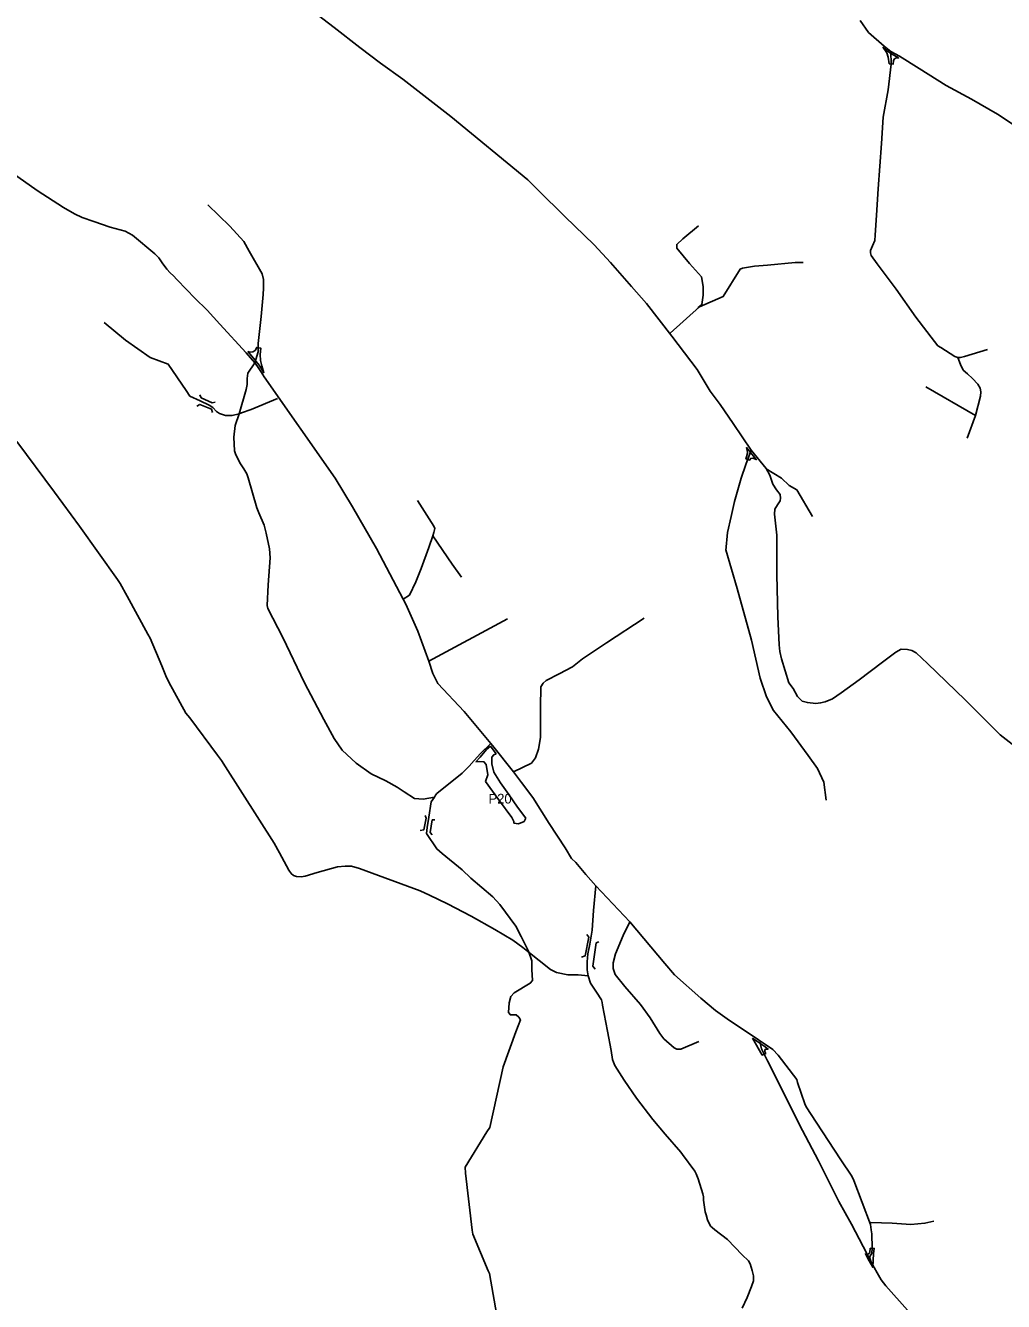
# Model space of a CAD drawing. Extents: x -439169 to -431590, y -1130011 to -1121081.
# Drawn here: x -437746 to -436739, y -1125656 to -1124342 of the extents above; entities that cross this region are included whole.
import ezdxf

# ---------------------------------------------------------------- set-up
doc = ezdxf.new("R2010")
doc.units = 0
for name, color, linetype in [('11811012_místní  komunikace_Stav', 7, 'Continuous'), ('11900012_účelová komunikace_Stav', 7, 'Continuous'), ('11930011_silniční most _ estakáda_Stav', 7, 'Continuous'), ('12080011_parkoviště mimo prostor komunikace_Stav', 7, 'Continuous'), ('12080013_parkoviště mimo prostor komunikace_Stav', 7, 'Continuous')]:
    doc.layers.add(name, color=color, linetype=linetype)

msp = doc.modelspace()

# ---------------------------------------------------------------- linework, layer by layer
at = {"layer": '11811012_místní  komunikace_Stav'}
msp.add_line((-437164.8, -1125287.2), (-437164.6, -1125287.3), dxfattribs=at)
for points in [[(-437450.2, -1124327.5), (-437428.1, -1124344.3), (-437401.6, -1124365), (-437380.4, -1124381), (-437357.4, -1124397.8), (-437307.9, -1124435.9), (-437228.9, -1124501.3), (-437218, -1124511.9), (-437190.5, -1124539), (-437160.3, -1124568.3), (-437143.6, -1124586.2), (-437122, -1124610.9), (-437106.5, -1124628.5), (-437080.4, -1124662.1), (-437054.4, -1124696.6), (-437041, -1124718.7), (-437030.6, -1124732.4), (-437017.3, -1124752), (-436999, -1124779.6), (-436983.5, -1124798.5), (-436979.6, -1124805.1), (-436976.6, -1124814.5), (-436972.9, -1124820.4), (-436968.9, -1124825.2), (-436968.5, -1124828.8), (-436969.1, -1124831.7), (-436971.6, -1124835.7), (-436974.4, -1124840.3), (-436974.8, -1124845.5), (-436972.3, -1124867), (-436972.4, -1124907.4), (-436971.3, -1124951), (-436969.9, -1124979.8), (-436969.3, -1124986.9), (-436967.7, -1124994.3), (-436960.1, -1125019.2), (-436955.8, -1125024.9), (-436951.2, -1125033.1), (-436948.4, -1125035.8), (-436946.3, -1125038), (-436940.9, -1125039.3), (-436932.4, -1125040.4), (-436927.4, -1125039.7), (-436922.6, -1125038.7), (-436915.3, -1125035.4), (-436906.1, -1125029.3), (-436887.6, -1125016), (-436863.8, -1124997.6), (-436850, -1124987.3), (-436844.6, -1124984.5), (-436838.1, -1124984.7), (-436833.4, -1124985.8), (-436829, -1124988.2), (-436817.2, -1124999.1), (-436778.5, -1125036.6), (-436742.4, -1125072.6), (-436719.4, -1125090.7)], [(-436886.5, -1124337.3), (-436878.1, -1124349.5), (-436861.8, -1124363.5), (-436855.1, -1124369), (-436846.2, -1124374), (-436826.1, -1124386.5), (-436798.3, -1124404.1), (-436772, -1124418.3), (-436745.3, -1124433.5), (-436718.8, -1124451)], [(-436855.1, -1124369), (-436854.7, -1124382.1), (-436857.8, -1124408.7), (-436863, -1124436.7), (-436864.8, -1124464), (-436868.3, -1124510.4), (-436869.8, -1124537.8), (-436871.1, -1124558.3), (-436871.7, -1124563.6), (-436873.9, -1124569.3), (-436875.9, -1124573.9), (-436875.9, -1124576.5), (-436875.2, -1124579.3), (-436869.3, -1124587.8), (-436849.7, -1124613.9), (-436829.5, -1124642.6), (-436810.3, -1124667.7), (-436806.6, -1124672.1), (-436803.5, -1124673.9), (-436789.1, -1124683.1), (-436786.2, -1124684.1), (-436783.4, -1124684.1), (-436779.3, -1124683), (-436755.7, -1124675.8)], [(-437765.4, -1124490), (-437733.7, -1124512.3), (-437706.7, -1124529.9), (-437695.5, -1124536.1), (-437687.3, -1124540.1), (-437675.5, -1124544.1), (-437658.6, -1124550), (-437643.3, -1124554), (-437635.8, -1124558.1), (-437612.8, -1124577.5), (-437608.5, -1124581.7), (-437605.2, -1124586.7), (-437600.2, -1124593.3), (-437596.8, -1124597), (-437593.5, -1124600.2), (-437590.1, -1124603.7), (-437580.2, -1124614.1), (-437571.6, -1124623.2), (-437558.9, -1124635.5), (-437545.8, -1124649.7), (-437518.6, -1124679.2), (-437509.8, -1124689.6), (-437506.9, -1124693.3), (-437503.6, -1124698.7), (-437500, -1124704), (-437427, -1124808.2), (-437409.2, -1124838), (-437384.4, -1124880.7), (-437357.2, -1124932.8), (-437354.4, -1124938), (-437342.1, -1124965.8), (-437330.7, -1124996.8), (-437326.4, -1125009.4), (-437323.4, -1125015.6), (-437321.3, -1125019.6), (-437294.2, -1125048.4), (-437266.8, -1125081.5), (-437265.2, -1125083.5), (-437243.4, -1125110.5), (-437235.1, -1125121.5), (-437223.7, -1125137.1), (-437206.8, -1125164), (-437190.2, -1125188.9), (-437183.8, -1125199.7), (-437179.5, -1125203.9), (-437169, -1125216.2), (-437158.8, -1125228), (-437123.6, -1125264.9), (-437087.6, -1125308), (-437077.9, -1125319.6), (-437050.7, -1125343.5), (-437035.4, -1125356.5), (-437021, -1125366.5)], [(-437509.8, -1124689.6), (-437506.4, -1124678.2), (-437506.4, -1124669.9), (-437504.9, -1124657.4), (-437503.2, -1124641.9), (-437501.2, -1124619.2), (-437500.7, -1124612.8), (-437500.7, -1124603.8), (-437502.2, -1124598.1), (-437515.6, -1124574.8), (-437521, -1124564.7), (-437535.5, -1124548.9), (-437558, -1124526.9)], [(-436999, -1124779.6), (-437004.3, -1124794.2), (-437009.3, -1124808.5), (-437016, -1124832.4), (-437019.6, -1124847.9), (-437023.3, -1124864.3), (-437024.8, -1124882.9)], [(-437266.8, -1125081.5), (-437277.4, -1125091.8), (-437283.9, -1125099.1), (-437289.1, -1125104.7), (-437296.2, -1125112), (-437322.3, -1125132.9), (-437323.9, -1125134.5), (-437324.9, -1125136.9), (-437328.2, -1125141.6), (-437330.8, -1125157.2), (-437332.2, -1125167.9), (-437332.9, -1125174.1), (-437322.5, -1125190), (-437316.9, -1125194.6), (-437296.3, -1125211.5), (-437287.5, -1125220)], [(-437021, -1125366.5), (-437003.1, -1125378.5), (-436991.4, -1125386.5), (-436984, -1125391.3), (-436976.5, -1125396.4), (-436970.9, -1125402.4), (-436952, -1125427.4), (-436951.1, -1125430.4), (-436943.5, -1125452.3), (-436942.4, -1125455.5), (-436932.1, -1125471.2), (-436906.5, -1125510.1), (-436895.4, -1125526.7), (-436893.2, -1125531.3), (-436875.9, -1125576.5), (-436875.2, -1125582.1), (-436874.5, -1125586.3), (-436874.3, -1125601.1), (-436874.8, -1125606), (-436877.1, -1125610.2), (-436875.2, -1125615.3)], [(-436989.8, -1125388.6), (-436988.1, -1125395.8), (-436982, -1125408.2), (-436967.8, -1125436.7), (-436949.6, -1125473.2), (-436929.7, -1125511.1), (-436908.5, -1125552.9), (-436895.6, -1125576.3), (-436883.7, -1125599.4), (-436875.2, -1125615.3), (-436869, -1125626.3), (-436864.9, -1125633.6), (-436860.3, -1125639.7), (-436854.6, -1125646.1), (-436806.8, -1125699.7)]]:
    msp.add_lwpolyline(points, dxfattribs=at)
for points in [[(-436856.7, -1124382), (-436857.8, -1124374.9), (-436859.3, -1124370.5), (-436863, -1124365), (-436856.2, -1124370.6), (-436847.2, -1124375.7), (-436849.5, -1124375.6), (-436851.8, -1124376.9), (-436852.4, -1124378.6), (-436852.7, -1124382.2)], [(-437517.1, -1124677.9), (-437514.4, -1124678.7), (-437511.7, -1124678.3), (-437509.4, -1124676.9), (-437507.7, -1124673.8), (-437503.7, -1124674.5), (-437504.4, -1124680.9), (-437503.9, -1124687.4), (-437502.5, -1124692.7), (-437500.5, -1124699.8), (-437503, -1124695.9), (-437505.3, -1124692.2), (-437512.8, -1124682.9)], [(-437003.6, -1124786.4), (-437002.8, -1124782.5), (-437003.1, -1124779.3), (-437003.8, -1124776.8), (-436993.6, -1124789.2), (-436995.3, -1124788.3), (-436997, -1124787.9), (-436999.3, -1124788.1), (-437000.5, -1124789.7), (-437004.3, -1124788.4)], [(-436997.5, -1125384.9), (-436987.5, -1125402.3), (-436983.9, -1125400.5), (-436984.7, -1125398.6), (-436984.7, -1125397.3), (-436984.2, -1125396.3), (-436983.1, -1125396), (-436981.5, -1125396), (-436985.7, -1125392.7), (-436990.8, -1125389.2)], [(-436876.3, -1125601), (-436872.2, -1125601.2), (-436872.9, -1125606.6), (-436873.7, -1125620.7), (-436878.4, -1125612.2), (-436881.3, -1125606.7), (-436879.4, -1125607.4), (-436878.1, -1125607.3), (-436877.4, -1125606.2), (-436876.8, -1125605.4)]]:
    msp.add_lwpolyline(points, close=True, dxfattribs=at)
at = {"layer": '11900012_účelová komunikace_Stav'}
for p, q in [((-436819.1, -1124714.3), (-436767.8, -1124743.8)), ((-437330.7, -1124996.8), (-437249.6, -1124953))]:
    msp.add_line(p, q, dxfattribs=at)
for points in [[(-437053.6, -1124633.1), (-437049.7, -1124629.5), (-437048.2, -1124619.9), (-437048.2, -1124611), (-437050.1, -1124601), (-437062.3, -1124587.4), (-437075.5, -1124571.5), (-437075.5, -1124567.8), (-437069.3, -1124561.9), (-437053, -1124548.7)], [(-437082.1, -1124659.2), (-437052, -1124632.1), (-437027.6, -1124621.4), (-437010.1, -1124593.2), (-437007.9, -1124592.2), (-436995.4, -1124590.2), (-436982.2, -1124589.1), (-436953.7, -1124586.5), (-436945.2, -1124586.2)], [(-437486.3, -1124726.5), (-437513.5, -1124737.8), (-437523.5, -1124741.1), (-437525.8, -1124742), (-437533.1, -1124743.8), (-437539.9, -1124743.9), (-437546, -1124741.8), (-437549.1, -1124739.6), (-437553, -1124735.7), (-437556.7, -1124733.2), (-437565.9, -1124728.7), (-437576.6, -1124723.8), (-437580.3, -1124718), (-437598.8, -1124691.1), (-437617.6, -1124684.2), (-437642.9, -1124666.3), (-437664.7, -1124648.2)], [(-437509.8, -1124689.6), (-437517, -1124700.3), (-437517.7, -1124705.9), (-437517.7, -1124711.9), (-437518.5, -1124717.1), (-437525.8, -1124742), (-437529.9, -1124754), (-437531.2, -1124766.3), (-437530.5, -1124780.3), (-437529.2, -1124784.4), (-437524.4, -1124793.6), (-437520.9, -1124798.6), (-437517.9, -1124803.9), (-437516.6, -1124808.1), (-437507.8, -1124838.9), (-437505.6, -1124844.2), (-437500, -1124856.6), (-437498.2, -1124865.1), (-437494.5, -1124881.2), (-437494, -1124890.3), (-437496, -1124918.3), (-437497.1, -1124939.6), (-437496.4, -1124942.4), (-437480.9, -1124972.5), (-437458.6, -1125018.9), (-437438.7, -1125056.8), (-437428, -1125076.2), (-437419.9, -1125088.4), (-437405.5, -1125101.9), (-437390, -1125112.7), (-437375, -1125119.9), (-437363.2, -1125126.4), (-437355.9, -1125131.2), (-437345.5, -1125138.1), (-437336.4, -1125138.8), (-437324.9, -1125136.9)], [(-436786.2, -1124684.1), (-436783.3, -1124691.4), (-436780.6, -1124697.1), (-436776.3, -1124700.8), (-436771.2, -1124705.8), (-436765.6, -1124711.5), (-436763.2, -1124715.8), (-436762.3, -1124719.4), (-436762.9, -1124723.9), (-436767.8, -1124743.8), (-436776.6, -1124767.3)], [(-437754.8, -1124770.6), (-437715.9, -1124822.9), (-437690.1, -1124857.9), (-437651.2, -1124912.5), (-437648.3, -1124916.7), (-437641.1, -1124929.8), (-437619.8, -1124968.8), (-437617.5, -1124972.9), (-437605.4, -1125001.6), (-437601.5, -1125012), (-437598.2, -1125018.3), (-437580.7, -1125050.2), (-437576.5, -1125055.2), (-437548.1, -1125093.5), (-437544.2, -1125099.1), (-437539.8, -1125105.5), (-437489.9, -1125184.2), (-437484.5, -1125193.9), (-437474.9, -1125212), (-437472.4, -1125215.3), (-437469.8, -1125217.4), (-437466.7, -1125218.5), (-437462.2, -1125218.8), (-437458, -1125218.1), (-437445.6, -1125214.2), (-437424.8, -1125208.3), (-437416.7, -1125207.6), (-437410.1, -1125207.8), (-437402, -1125210.3), (-437339.6, -1125233.1), (-437330.1, -1125237.6), (-437311.5, -1125246.6), (-437287.1, -1125259.1), (-437262.7, -1125272.9), (-437244.1, -1125284), (-437234, -1125291.6), (-437228.8, -1125295.6), (-437205.3, -1125314), (-437199.2, -1125317.3), (-437187.6, -1125319.6), (-437176.9, -1125319.6), (-437166.5, -1125320.8)], [(-436983.3, -1124798.8), (-436967.8, -1124808.2), (-436959.6, -1124815.8), (-436951.8, -1124820.4), (-436935.9, -1124847.7)], [(-437357.2, -1124932.8), (-437350.7, -1124928.7), (-437344.1, -1124915.1), (-437338.5, -1124901.2), (-437330.8, -1124879.6), (-437326.6, -1124867.7), (-437325.5, -1124864.4), (-437324.5, -1124860.2), (-437325.5, -1124857.6), (-437342.4, -1124831.2)], [(-437326.6, -1124867.7), (-437306.5, -1124897), (-437297.1, -1124910.1)], [(-437024.8, -1124882.2), (-437013.3, -1124922), (-436998.5, -1124975.1), (-436989.7, -1125014.2), (-436983, -1125033.4), (-436975.7, -1125047.4), (-436958, -1125069.6), (-436940.3, -1125093.9), (-436930.7, -1125107.2), (-436924, -1125121.2), (-436921.8, -1125139.7)], [(-437243.4, -1125110.5), (-437225, -1125101.6), (-437220.9, -1125096.1), (-437217.6, -1125087.2), (-437215.8, -1125075.4), (-437215.8, -1125044.1), (-437215.4, -1125023.1), (-437213.1, -1125019.4), (-437209.9, -1125016.8), (-437196.6, -1125009.8), (-437182.6, -1125002.4), (-437172.6, -1124994.3), (-437147.9, -1124977.7), (-437108.9, -1124952.3)], [(-437287.5, -1125220), (-437264.8, -1125239.3), (-437257.5, -1125247.1), (-437241.2, -1125269.6), (-437235.7, -1125280), (-437228.2, -1125295.1), (-437224.6, -1125305.3), (-437224.6, -1125314.1), (-437224.1, -1125325.4), (-437226.3, -1125328.3), (-437242.8, -1125338.2), (-437246.1, -1125342), (-437248, -1125348.6), (-437248.7, -1125358.3), (-437246.6, -1125360.9), (-437240.9, -1125360.7), (-437238.1, -1125363.1), (-437236.4, -1125366.1), (-437241.2, -1125378.2), (-437254.2, -1125414.4), (-437267.7, -1125476.7), (-437270.8, -1125481.2), (-437293.2, -1125517.6), (-437293, -1125523.8), (-437286.1, -1125582.5), (-437285.3, -1125586.5), (-437269.5, -1125624.4), (-437268.2, -1125627.2), (-437259.6, -1125676.1)], [(-437158.8, -1125228), (-437161.1, -1125253.3), (-437162.4, -1125273.8), (-437165, -1125287.9), (-437166.9, -1125298.1), (-437167.5, -1125306.4), (-437167.5, -1125314.3), (-437166.5, -1125320.8), (-437164.1, -1125328.3), (-437158.2, -1125337.5), (-437152.9, -1125345.5), (-437152.3, -1125348), (-437151.8, -1125350.8), (-437146.8, -1125377.7), (-437143.1, -1125397.6), (-437141.5, -1125406.7), (-437140.4, -1125409.5), (-437139.1, -1125413), (-437129.5, -1125428.1), (-437117, -1125446.6), (-437100.2, -1125468.4), (-437087.5, -1125483.7), (-437071.3, -1125502.2), (-437069.6, -1125504.6), (-437056.8, -1125521.8), (-437055.3, -1125524.6), (-437053.4, -1125529.7), (-437048.5, -1125545), (-437047.9, -1125548), (-437047.9, -1125551.7), (-437046.3, -1125563.5), (-437045.3, -1125566.8), (-437043.7, -1125571.8), (-437040.8, -1125578.2), (-437038.9, -1125579.8), (-437036.1, -1125582.2), (-437023.1, -1125592), (-437008.1, -1125607.9), (-437001.7, -1125613.9), (-436999.9, -1125617.2), (-436998, -1125624), (-436996.5, -1125629.6), (-436996.5, -1125634.7), (-436998.4, -1125640.3), (-437003, -1125651.7), (-437008.1, -1125662.9)], [(-437123.6, -1125264.9), (-437130.5, -1125279), (-437138.4, -1125297.9), (-437140.8, -1125307.3), (-437141, -1125313.1), (-437138.8, -1125319.4), (-437128.8, -1125331.6), (-437112.8, -1125350), (-437102.7, -1125364), (-437092.7, -1125380), (-437088.7, -1125385.4), (-437078, -1125394.9), (-437075.5, -1125396), (-437071.2, -1125396), (-437052.8, -1125388.4)], [(-436875.7, -1125574.4), (-436853.6, -1125575.4), (-436834.4, -1125576.5), (-436820, -1125575.4), (-436810.8, -1125573.1)]]:
    msp.add_lwpolyline(points, dxfattribs=at)
at = {"layer": '11930011_silniční most _ estakáda_Stav'}
for points in [[(-437569.4, -1124734.3), (-437566.4, -1124732.4), (-437554.2, -1124737.4), (-437553.3, -1124740.9)], [(-437566.4, -1124722.5), (-437564.9, -1124725.6), (-437553.7, -1124730.8), (-437550.7, -1124730)], [(-437334.5, -1125155.6), (-437333.4, -1125158.2), (-437335.8, -1125170.4), (-437339.6, -1125171.1)], [(-437324.5, -1125159.9), (-437327.1, -1125160.2), (-437329.3, -1125173.1), (-437327.1, -1125175.5)], [(-437168.1, -1125278.1), (-437166.1, -1125280.7), (-437169.6, -1125299.9), (-437173.5, -1125301.3)], [(-437155.8, -1125285.7), (-437158.3, -1125286.8), (-437161.7, -1125310.7), (-437159.4, -1125313.7)]]:
    msp.add_lwpolyline(points, dxfattribs=at)
at = {"layer": '12080011_parkoviště mimo prostor komunikace_Stav'}
msp.add_line((-437243.1, -1125163.5), (-437238.4, -1125164.1), dxfattribs=at)
for points in [[(-437267.2, -1125084.4), (-437271.3, -1125087.7), (-437277.8, -1125095.4), (-437282.2, -1125100.2)], [(-437261.2, -1125092.1), (-437267.2, -1125084.4)], [(-437282.2, -1125100.2), (-437279, -1125100), (-437274, -1125100.3), (-437271.6, -1125103), (-437270, -1125113.8), (-437272.4, -1125120.6)], [(-437230.7, -1125158.3), (-437239.3, -1125147.1), (-437248.4, -1125134), (-437256.8, -1125122.1), (-437263.8, -1125110.9), (-437265.7, -1125102.4), (-437265.8, -1125095.7), (-437263.9, -1125093.3), (-437261.2, -1125092.1)], [(-437272.4, -1125120.6), (-437257.9, -1125140.4)], [(-437257.9, -1125140.4), (-437245.2, -1125157.5), (-437243.1, -1125161.7), (-437243.1, -1125163.5)], [(-437238.4, -1125164.1), (-437232.4, -1125161.7)], [(-437232.4, -1125161.7), (-437230.7, -1125158.3)]]:
    msp.add_lwpolyline(points, dxfattribs=at)

# ---------------------------------------------------------------- texts
at = {"layer": '12080013_parkoviště mimo prostor komunikace_Stav'}
msp.add_text('P20', height=10, dxfattribs=at).set_placement((-437269.2, -1125143.3))

doc.saveas('drawing.dxf')
